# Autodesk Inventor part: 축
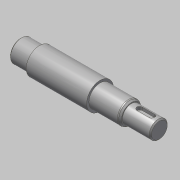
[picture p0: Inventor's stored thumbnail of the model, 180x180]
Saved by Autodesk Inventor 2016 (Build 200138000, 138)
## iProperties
Created: 2016-06
Part Number: 축
Material: 강철, 연강
Document SubType Name: Modeling
Designer: mduedu
Density: 7.86 g/cm^3
Appearance: 강철
Mass: 339.086 g
Surface Area: 91.4411 cm^2
Volume: 43.1408 cm^3
Author: mduedu
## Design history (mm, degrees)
sketch "스케치1"
  geometry: L1 (-62, 0)-(62, 0); L2 (-62, 0)-(-62, 10); L3 (-62, 10)-(-45, 10); L4 (-45, 10)-(-45, 12); L5 (-45, 12)-(9, 12); L6 (9, 12)-(9, 10); L7 (9, 10)-(37, 10); L8 (37, 10)-(37, 8); L9 (37, 8)-(62, 8); L10 (62, 8)-(62, 0); 2 further points
  constraints: 20 end point, 5 parallel, 2 perpendicular, 1 coincident, 1 collinear, 1 horizontal, 1 midpoint, 1 vertical
  dimensions: "d0" = 124 distance of L1.start L1.end; "d2" = 16 diameter of L9 L1; "d3" = 20 diameter of L7 L1; "d4" = 24 diameter of L5 L1; "d5" = 20 diameter of L3 L1; "d6" = 17 distance of L2.end L3.end; "d7" = 25 distance of L8.end L9.end; "d8" = 53 distance from line of L5.end L10
revolve "회전1" sketch "스케치1" stored, may be unused: angle "d9" = 90 deg
chamfer "모따기1" distance "d10" = 2; stored, may be unused: second distance "d11" = 2, angle "d12" = 30 deg
fillet "모깎기1" dims "d13" = 2
node "작업 평면1"
sketch "스케치2"
  geometry: L1 (-5, 2.5)-(6, 2.5); L2 (6, -2.5)-(-5, -2.5); L3 (-5, 0)-(6, 0); L4 (-12.5, 8.845)-(-12.5, -8.845) reference; A1 r 2.5 centre (-5, 0) between (-5, 2.5) and (-5, -2.5); A2 r 2.5 centre (6, 0) between (6, -2.5) and (6, 2.5); 1 further point
  constraints: 6 end point, 4 point on circle, 3 tangent, 2 centre point, 2 parallel, 1 horizontal, 1 horizontal alignment
  dimensions: "d14" = 5 distance edge to line of A1 L4; "d15" = 5 distance between parallel lines of L2 L1; "d16" = 16 dimension on A2 A1
extrude "돌출1" cut sketch "스케치2" distance "d17" = 3; taper "d18" = 0 deg
chamfer "모따기2" distance "d19" = 1; stored, may be unused: second distance "d20" = 2, angle "d21" = 30 deg
sketch "스케치3"
  geometry: L1 (-37, -8)-(-61, -8) reference; L2 (-62, -7)-(-62, 7) reference; L3 (-38.5, -8)-(-40, -6.5); L4 (-40, -6.5)-(-40, -8); L5 (-38.5, -8)-(-40, -8); 1 further point
  constraints: 6 end point, 2 point on line, 1 collinear, 1 vertical
  dimensions: "d22" = 45 deg angle of L4 L3; "d23" = 22 distance between parallel lines of L2 L4; "d24" = 3 diameter of L3.start L4
revolve "회전2" stored, may be unused: angle "d25" = 90 deg
node "작업점1"
sketch "스케치4"
  geometry: 1 further point
hole "구멍1" sketch "스케치4" at (0, 0) diameter "d26" = 3.242; stored, may be unused: countersink angle "d30" = 90 deg, drill point angle "d32" = 120 deg; dims "d27" = 8, "d28" = 4, "d29" = 2, "d31" = 11
chamfer "모따기3" distance "d33" = 2; stored, may be unused: second distance "d34" = 2, angle "d35" = 30 deg
node "솔리드1"
